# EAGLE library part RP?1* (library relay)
Power PCB Relay RP II/1 SCHRACK 1 pole 16 A Source: http://www.schrack.com/.. 5834.pdf
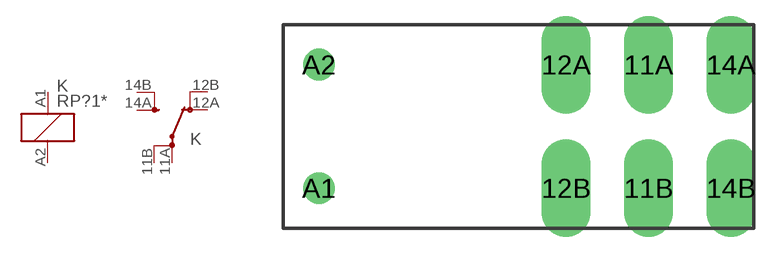
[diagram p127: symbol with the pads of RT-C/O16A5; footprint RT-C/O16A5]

Designator prefix K; gates 1=K 2=U-X2

## RP310005 (MPN: RP310005; OC_FARNELL: unknown; OC_NEWARK: 48M7769), RP310006 (MF: TYCO ELECTRONICS; MPN: RP310006; OC_FARNELL: unknown; OC_NEWARK: 08H3568), RP310012 (MF: FARNELL; MPN: RP310012.; OC_FARNELL: 388294; OC_NEWARK: 87H7751), RP310024 (MF: TYCO ELECTRONICS; MPN: RP310024; OC_FARNELL: 1838950; OC_NEWARK: 17M1783), RP310048 (MF: TYCO ELECTRONICS; MPN: RP310048; OC_FARNELL: unknown; OC_NEWARK: 08H3569), RP310060 (OC_FARNELL: unknown; OC_NEWARK: unknown), RP310110 (MF: TYCO ELECTRONICS; MPN: RP310110; OC_FARNELL: unknown; OC_NEWARK: 97C5675)  [RT-C/O16A5]
11A  2:PA  pas
11B  2:PB  pas
12A  2:OA  pas
12B  2:OB  pas
14A  2:SA  pas
14B  2:SB  pas
A1  1:1  pas
A2  1:2  pas

## RP710005 (MF: TYCO ELECTRONICS; MPN: RP710005; OC_FARNELL: unknown; OC_NEWARK: 52F964), RP710006 (MF: TYCO ELECTRONICS; MPN: RP710006; OC_FARNELL: unknown; OC_NEWARK: 08H3633), RP710012 (MF: FARNELL; MPN: RP710012; OC_FARNELL: 388312; OC_NEWARK: 50H2650), RP710024 (MF: TYCO ELECTRONICS; MPN: RP710024; OC_FARNELL: 388324; OC_NEWARK: 17M1785), RP710048 (MPN: RP710048; OC_FARNELL: unknown; OC_NEWARK: 48M7825), RP710060 (OC_FARNELL: unknown; OC_NEWARK: unknown), RP710110 (OC_FARNELL: unknown; OC_NEWARK: unknown)  [RT-C/O16A5]
Pads as for RT-C/O16A5

## Footprint RT-C/O16A5 (pad centres in mm)
Power PCB Relay 1 pole 12 / 16 A, DC- or AC-coil SCHRACK 16 A, pinning 5mm Source: http://www.schrack.com/.. 5819.pdf
drill 1.3 pad 3 long: 11A 7.56,3.78; 11B 7.56,-3.78; 12A 2.52,3.78; 12B 2.52,-3.78; 14A 12.6,3.78; 14B 12.6,-3.78
drill 1.3 round: A1 -12.6,-3.78; A2 -12.6,3.78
